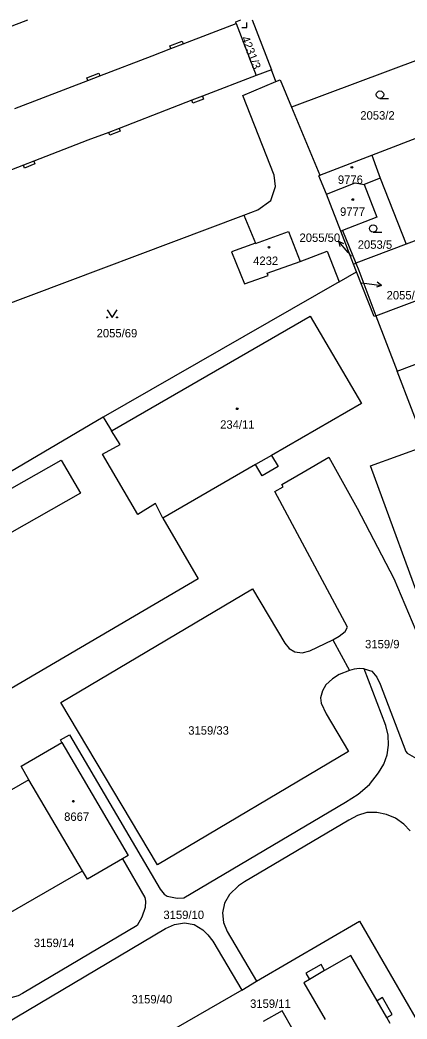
# Model space of a CAD drawing. Extents: x -564952 to -564307, y -1202373 to -1201847.
# Drawn here: x -564808.4 to -564730.1, y -1202052.1 to -1201850.1 of the extents above; entities that cross this region are included whole.
import ezdxf

# ---------------------------------------------------------------- set-up
doc = ezdxf.new("R2010")
doc.units = 0
for name, color, linetype in [('Hranice parcel', 7, 'Continuous'), ('Parcelní čísla', 7, 'Continuous'), ('Pop  PČ popisy', 7, 'Continuous'), ('Vnitřní kresba', 7, 'Continuous'), ('Značky budov', 7, 'Continuous'), ('Značky kultur', 7, 'Continuous')]:
    doc.layers.add(name, color=color, linetype=linetype)

msp = doc.modelspace()

# ---------------------------------------------------------------- linework, layer by layer
at = {"layer": 'Hranice parcel'}
for p, q in [((-564764.67, -1201850.76), (-564760.61, -1201861.29)), ((-564761.45, -1201850.07), (-564757.57, -1201860.17)), ((-564757.57, -1201860.17), (-564760.61, -1201861.29)), ((-564737.23, -1201877.39), (-564703.52, -1201864.46)), ((-564747.75, -1201881.47), (-564737.23, -1201877.39)), ((-564735.84, -1201881.33), (-564735.58, -1201882.08)), ((-564735.58, -1201882.08), (-564738.82, -1201883.3)), ((-564738.82, -1201883.3), (-564736.24, -1201889.91)), ((-564735.58, -1201882.08), (-564730.34, -1201895.42)), ((-564743.54, -1201892.77), (-564746.43, -1201885.3)), ((-564815.66, -1201909.3), (-564763.15, -1201889.53)), ((-564763.15, -1201889.53), (-564760.79, -1201895.19)), ((-564736.24, -1201889.91), (-564743.19, -1201892.63)), ((-564743.19, -1201892.63), (-564743.54, -1201892.77)), ((-564740.95, -1201899.44), (-564743.54, -1201892.77)), ((-564743.19, -1201892.63), (-564740.48, -1201899.26)), ((-564760.79, -1201895.19), (-564760.76, -1201895.27)), ((-564730.34, -1201895.42), (-564740.48, -1201899.26)), ((-564758.39, -1201901.26), (-564751.74, -1201898.89)), ((-564740.95, -1201899.44), (-564740.48, -1201899.26)), ((-564740.34, -1201900.99), (-564740.95, -1201899.44)), ((-564740.48, -1201899.26), (-564739.88, -1201900.72)), ((-564736.45, -1201909.86), (-564710.02, -1201899.92)), ((-564758.24, -1201901.7), (-564758.39, -1201901.26)), ((-564743.83, -1201903.01), (-564740.34, -1201900.99)), ((-564736.81, -1201909.99), (-564740.34, -1201900.99)), ((-564739.88, -1201900.72), (-564736.45, -1201909.86)), ((-564743.83, -1201903.01), (-564791.55, -1201930.35)), ((-564736.45, -1201909.86), (-564736.81, -1201909.99)), ((-564736.45, -1201909.86), (-564732.16, -1201921.04)), ((-564732.16, -1201921.04), (-564722.24, -1201917.34)), ((-564726.36, -1201936.19), (-564732.16, -1201921.04)), ((-564791.55, -1201930.35), (-564815.05, -1201944.22)), ((-564791.55, -1201930.35), (-564791.22, -1201930.91)), ((-564791.22, -1201930.91), (-564789.91, -1201933.12)), ((-564745.15, -1201975.39), (-564743.87, -1201974.68)), ((-564749.79, -1201977.59), (-564745.15, -1201975.39)), ((-564745.15, -1201975.39), (-564741.77, -1201981.57)), ((-564741.77, -1201981.57), (-564743.83, -1201982.39)), ((-564740.81, -1201981.32), (-564741.77, -1201981.57)), ((-564795.75, -1202022.1), (-564806.58, -1202003.73)), ((-564821.79, -1202037.08), (-564795.75, -1202022.1)), ((-564763.53, -1202046.19), (-564760.54, -1202044.37)), ((-564763.53, -1202046.19), (-564781.32, -1202056.49))]:
    msp.add_line(p, q, dxfattribs=at)
for points in [[(-564945.44, -1201903.37), (-564935.91, -1201899.81), (-564919.07, -1201893.35), (-564902.1, -1201886.82), (-564883.7, -1201879.64), (-564866.22, -1201872.94), (-564849.42, -1201866.53), (-564817.27, -1201854.05), (-564806.83, -1201850.07)], [(-564809.42, -1201868), (-564798.7, -1201863.87), (-564794.68, -1201862.32), (-564794.89, -1201861.76), (-564792.42, -1201860.8), (-564792.21, -1201861.37), (-564781.67, -1201857.31), (-564777.86, -1201855.84), (-564778.08, -1201855.28), (-564775.62, -1201854.33), (-564775.4, -1201854.89), (-564764.67, -1201850.76)], [(-564764.67, -1201850.76), (-564764.78, -1201850.47), (-564763.74, -1201850.07)], [(-564727.38, -1201857.94), (-564753.52, -1201867.7), (-564747.75, -1201881.47)], [(-564760.61, -1201861.29), (-564771.5, -1201865.49), (-564771.28, -1201866.06), (-564773.41, -1201866.87), (-564773.62, -1201866.3), (-564777.63, -1201867.85), (-564788.36, -1201871.98), (-564788.15, -1201872.53), (-564790.25, -1201873.33), (-564790.45, -1201872.79), (-564794.64, -1201874.4), (-564805.58, -1201878.62), (-564805.37, -1201879.18), (-564807.46, -1201880.01), (-564807.69, -1201879.43), (-564811.66, -1201880.96)], [(-564763.15, -1201889.53), (-564760.29, -1201888.48), (-564757.69, -1201886.54), (-564756.7, -1201883.73), (-564757.02, -1201881.45), (-564763.35, -1201865.34), (-564756.66, -1201862.54), (-564757.57, -1201860.17)], [(-564737.23, -1201877.39), (-564736.1, -1201880.6), (-564735.84, -1201881.33)], [(-564746.43, -1201885.3), (-564747.96, -1201881.55), (-564747.75, -1201881.47)], [(-564746.43, -1201885.3), (-564740.63, -1201882.99), (-564738.82, -1201883.3)], [(-564716.1, -1201888.41), (-564715.57, -1201889.81), (-564716.6, -1201890.2), (-564730.34, -1201895.42)], [(-564760.76, -1201895.27), (-564754.08, -1201892.83), (-564751.74, -1201898.89)], [(-564760.79, -1201895.19), (-564765.6, -1201896.95), (-564762.99, -1201903.39), (-564758.24, -1201901.7)], [(-564751.74, -1201898.89), (-564746.29, -1201896.84), (-564743.83, -1201903.01)], [(-564789.91, -1201933.12), (-564789.78, -1201933.05), (-564749.69, -1201909.97), (-564739.38, -1201927.64)], [(-564739.38, -1201927.64), (-564757.51, -1201938.09), (-564756.2, -1201940.36), (-564759.46, -1201942.24), (-564760.77, -1201939.97), (-564779.51, -1201950.78)], [(-564779.51, -1201950.78), (-564781.01, -1201947.86), (-564784.53, -1201950.07), (-564791.7, -1201937.82), (-564788.15, -1201935.92), (-564789.91, -1201933.12)], [(-564711.3, -1202011.73), (-564714.18, -1202003.86), (-564737.5, -1201940.24), (-564726.36, -1201936.19)], [(-564743.87, -1201974.68), (-564742.68, -1201973.7), (-564742.16, -1201972.86), (-564756.86, -1201945.42), (-564755.16, -1201944.44), (-564755.45, -1201943.97), (-564751.11, -1201941.46), (-564745.96, -1201938.44), (-564740.22, -1201948.79), (-564732.79, -1201962.98), (-564725.4, -1201980.52), (-564719.8, -1201995.48), (-564706.71, -1202031.28)], [(-564800.09, -1201939.05), (-564796.12, -1201945.76), (-564854.09, -1201978.63), (-564857.91, -1201971.86), (-564800.09, -1201939.05)], [(-564779.51, -1201950.78), (-564772.34, -1201963.08), (-564900.66, -1202038.24)], [(-564743.83, -1201982.39), (-564745.2, -1201983.26), (-564746.54, -1201984.49), (-564747.25, -1201985.72), (-564747.62, -1201987.12), (-564747.48, -1201988.22), (-564746.47, -1201990.32), (-564741.99, -1201997.94), (-564780.59, -1202020.87), (-564800.1, -1201988.03), (-564761.36, -1201965.11), (-564754.85, -1201976.09), (-564753.96, -1201977.14), (-564752.8, -1201977.83), (-564751.35, -1201978.02), (-564749.79, -1201977.59)], [(-564799.95, -1201996.14), (-564800.21, -1201995.63), (-564798.4, -1201994.58), (-564780.02, -1202025.79), (-564779.27, -1202026.81), (-564778.6, -1202027.22), (-564776.64, -1202027.64), (-564775.28, -1202027.57), (-564742.59, -1202008.18), (-564740.02, -1202006.61), (-564737.76, -1202004.62), (-564735.9, -1202002.27), (-564734.86, -1202000.53), (-564734.18, -1201998.64), (-564733.88, -1201996.66), (-564733.95, -1201994.67), (-564734.46, -1201992.7), (-564738.81, -1201981.26)], [(-564738.81, -1201981.26), (-564739.75, -1201981.22), (-564740.81, -1201981.32)], [(-564738.81, -1201981.26), (-564737.28, -1201981.76), (-564736.22, -1201982.93), (-564735.6, -1201984.35), (-564730.37, -1201997.98), (-564730.11, -1201998.29), (-564728.24, -1201999.36), (-564725.88, -1202000.98), (-564723.7, -1202002.98), (-564723.06, -1202004.34), (-564722.79, -1202005.32), (-564722.8, -1202006.77), (-564723.36, -1202008.7), (-564724.79, -1202011.36), (-564715.88, -1202036.65), (-564712.4, -1202035.41), (-564711.8, -1202035.46), (-564711.42, -1202035.78), (-564710.52, -1202038.26), (-564709.8, -1202041.19), (-564709.53, -1202045.2), (-564709.81, -1202049.19), (-564710.38, -1202053.2), (-564711.28, -1202057.08)], [(-564806.58, -1202003.73), (-564808.13, -1202000.94), (-564799.95, -1201996.14)], [(-564799.95, -1201996.14), (-564786.51, -1202018.98), (-564787.67, -1202019.66)], [(-564806.58, -1202003.73), (-564846.76, -1202026.84), (-564836.11, -1202045.3), (-564830.52, -1202042.04), (-564829.18, -1202044.37), (-564823.87, -1202041.31)], [(-564729.54, -1202014), (-564730.82, -1202012.69), (-564732.44, -1202011.48), (-564734.3, -1202010.7), (-564736.24, -1202010.27), (-564738.26, -1202010.32), (-564740.14, -1202010.94), (-564741.94, -1202011.87), (-564763.02, -1202024.34), (-564764.24, -1202025.11), (-564766.05, -1202026.87), (-564767.06, -1202028.6), (-564767.44, -1202030.56), (-564767.25, -1202032.57), (-564766.47, -1202034.37), (-564760.54, -1202044.37)], [(-564787.67, -1202019.66), (-564783.16, -1202027.51), (-564783, -1202028.26), (-564783.1, -1202029.51), (-564783.72, -1202031.45), (-564784.69, -1202033.14), (-564807.89, -1202046.9), (-564808.78, -1202047.36), (-564810.26, -1202047.79), (-564812.29, -1202047.82), (-564814.21, -1202047.24), (-564815.98, -1202046.17), (-564817.26, -1202044.62)], [(-564787.67, -1202019.66), (-564794.74, -1202023.76), (-564795.75, -1202022.1)], [(-564860.22, -1202082.01), (-564778.94, -1202033.78), (-564777.13, -1202032.93), (-564775.15, -1202032.6), (-564773.15, -1202032.93), (-564771.45, -1202034.01), (-564770.42, -1202035.04), (-564769.41, -1202036.32), (-564763.53, -1202046.19)], [(-564760.54, -1202044.37), (-564739.77, -1202032.27), (-564725.85, -1202056.25), (-564767.37, -1202080.44)], [(-564733.18, -1202051.17), (-564735.1, -1202047.72), (-564736.21, -1202048.36), (-564741.52, -1202039.2), (-564746.8, -1202042.27), (-564747.53, -1202041.01), (-564750.61, -1202042.8), (-564749.88, -1202044.06), (-564751.01, -1202044.71), (-564746.68, -1202052.16)], [(-564753.16, -1202054.28), (-564755.38, -1202050.37), (-564759.2, -1202052.55)], [(-564733.54, -1202052.94), (-564734.23, -1202051.78), (-564733.18, -1202051.17)]]:
    msp.add_lwpolyline(points, dxfattribs=at)
at = {"layer": 'Pop  PČ popisy'}
for p, q in [((-564742.04, -1201897.08), (-564744.01, -1201894.81)), ((-564744.01, -1201894.81), (-564742.97, -1201895.24)), ((-564744.01, -1201894.81), (-564743.73, -1201895.9)), ((-564741.37, -1201897.85), (-564742.04, -1201897.08)), ((-564739.26, -1201903.23), (-564738.25, -1201903.36)), ((-564738.25, -1201903.36), (-564735.27, -1201903.73)), ((-564735.27, -1201903.73), (-564736.33, -1201904.1)), ((-564735.27, -1201903.73), (-564736.2, -1201903.11))]:
    msp.add_line(p, q, dxfattribs=at)
at = {"layer": 'Vnitřní kresba'}
for p, q in [((-564777.86, -1201855.84), (-564775.4, -1201854.89)), ((-564794.68, -1201862.32), (-564792.21, -1201861.37)), ((-564756.66, -1201862.54), (-564755.81, -1201862.19)), ((-564755.81, -1201862.19), (-564753.52, -1201867.7)), ((-564771.5, -1201865.49), (-564773.62, -1201866.3)), ((-564788.36, -1201871.98), (-564790.45, -1201872.79)), ((-564805.58, -1201878.62), (-564807.69, -1201879.43)), ((-564757.51, -1201938.09), (-564760.77, -1201939.97)), ((-564746.8, -1202042.27), (-564749.88, -1202044.06)), ((-564734.23, -1202051.78), (-564736.21, -1202048.36))]:
    msp.add_line(p, q, dxfattribs=at)
at = {"layer": 'Značky budov'}
for centre in [(-564741.28, -1201879.87), (-564741.11, -1201886.38), (-564758.05, -1201896.02), (-564764.47, -1201928.68), (-564797.59, -1202008.03)]:
    msp.add_circle(centre, 0.175, dxfattribs=at)
at = {"layer": 'Značky kultur'}
for p, q in [((-564763.56, -1201851.61), (-564762.56, -1201851.61)), ((-564762.56, -1201851.61), (-564762.56, -1201850.61)), ((-564735.61, -1201865.92), (-564733.86, -1201865.92)), ((-564737, -1201892.97), (-564735.25, -1201892.97))]:
    msp.add_line(p, q, dxfattribs=at)
msp.add_lwpolyline([(-564790.77, -1201908.7), (-564789.77, -1201910.2), (-564788.77, -1201908.7)], dxfattribs=at)
for centre, radius in [((-564735.61, -1201865.17), 0.75), ((-564737, -1201892.22), 0.75), ((-564790.77, -1201910.2), 0.1), ((-564788.77, -1201910.2), 0.1)]:
    msp.add_circle(centre, radius, dxfattribs=at)

# ---------------------------------------------------------------- texts
at = {"layer": 'Parcelní čísla'}
msp.add_text('4231/3', height=1.7, rotation=291, dxfattribs=at).set_placement((-564763.7, -1201853.72))
for s, p in [('2053/2', (-564739.59, -1201870.21)), ('9776', (-564744.12, -1201883.2)), ('9777', (-564743.68, -1201889.67)), ('2055/50', (-564751.88, -1201894.94)), ('2053/5', (-564740.11, -1201896.33)), ('4232', (-564761.25, -1201899.6)), ('2055/51', (-564734.27, -1201906.57)), ('2055/69', (-564792.89, -1201914.24)), ('234/11', (-564767.92, -1201932.71)), ('3159/9', (-564738.62, -1201977.11)), ('3159/33', (-564774.37, -1201994.56)), ('8667', (-564799.46, -1202012)), ('3159/10', (-564779.39, -1202031.84)), ('3159/14', (-564805.59, -1202037.51)), ('3159/40', (-564785.82, -1202048.9)), ('3159/11', (-564761.87, -1202049.8))]:
    msp.add_text(s, height=1.7, dxfattribs=at).set_placement(p)

doc.saveas('drawing.dxf')
